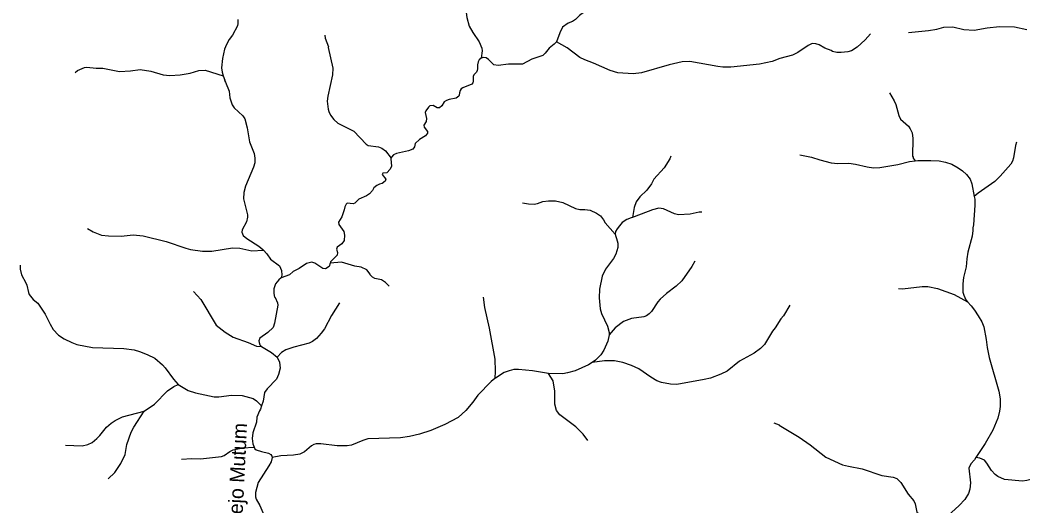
# Model space of a CAD drawing. Extents: x 280.4 to 335.6, y 8893.9 to 8949.5.
# Drawn here: x 296.15 to 309.86, y 8907.81 to 8914.46 of the extents above; entities that cross this region are included whole.
import ezdxf
from ezdxf.enums import TextEntityAlignment as Align

# ---------------------------------------------------------------- set-up
doc = ezdxf.new("R2010")
doc.units = 0
doc.header["$LTSCALE"] = 0.064
doc.layers.add('61', color=7, linetype='Continuous')
doc.layers.add('7', color=7, linetype='Continuous', lineweight=25)

msp = doc.modelspace()

# ---------------------------------------------------------------- linework, layer by layer
at = {"layer": '7'}
for points in [[(301.8848, 8915.449), (301.8864, 8915.4467), (301.9188, 8915.4138), (301.9677, 8915.3402), (302.0339, 8915.2193), (302.0645, 8915.1323), (302.0918, 8914.9596), (302.1185, 8914.8746), (302.1539, 8914.8139), (302.2065, 8914.7466), (302.2397, 8914.6644), (302.2609, 8914.4908), (302.2931, 8914.375), (302.3407, 8914.2893), (302.4311, 8914.1622), (302.4639, 8914.075), (302.4702, 8914.0389), (302.4566, 8913.937)], [(304.131, 8914.766), (304.1084, 8914.7319), (304.0128, 8914.6425), (303.8708, 8914.5712), (303.8022, 8914.5216), (303.7453, 8914.4656), (303.7067, 8914.4391), (303.647, 8914.4145), (303.5691, 8914.3586), (303.5316, 8914.284), (303.4874, 8914.1623)], [(299.1279, 8914.4677), (299.1312, 8914.4109), (299.1236, 8914.3786), (299.0589, 8914.2528), (299.013, 8914.191), (298.9749, 8914.1229), (298.9489, 8914.0583), (298.9185, 8913.9303), (298.9074, 8913.8032), (298.9143, 8913.7431), (298.9313, 8913.6938)], [(308.2977, 8914.2898), (308.572, 8914.3157), (308.6852, 8914.335), (308.7806, 8914.3588), (308.9026, 8914.3636), (309.0538, 8914.3285), (309.1977, 8914.3174), (309.3743, 8914.3527), (309.5424, 8914.3717), (309.7455, 8914.3651), (309.9167, 8914.3301)], [(300.3204, 8914.2503), (300.3254, 8914.21), (300.3674, 8914.0936), (300.3649, 8914.0806), (300.4296, 8913.7994), (300.4231, 8913.7082), (300.3596, 8913.4186), (300.3516, 8913.3507), (300.3628, 8913.2396), (300.3723, 8913.2066), (300.3969, 8913.1583), (300.44, 8913.0999), (300.4975, 8913.0484), (300.7149, 8912.9368), (300.8847, 8912.759), (300.9131, 8912.7414), (301.0536, 8912.7228), (301.0973, 8912.7065), (301.1489, 8912.6691), (301.2258, 8912.5692)], [(307.7771, 8914.2691), (307.7045, 8914.1858), (307.5982, 8914.0861), (307.5189, 8914.0364), (307.4698, 8914.0232), (307.3753, 8914.012), (307.3164, 8914.0152), (307.261, 8914.0289), (307.2411, 8914.0421), (307.1539, 8914.0725), (307.0773, 8914.1177), (307.0334, 8914.1343), (306.9818, 8914.1366), (306.9254, 8914.109), (306.7847, 8914.0132), (306.7133, 8913.9777), (306.5407, 8913.9308), (306.4328, 8913.8917), (306.2592, 8913.8523), (305.8713, 8913.8153), (305.7601, 8913.8154), (305.6929, 8913.8219), (305.3106, 8913.8914), (305.2028, 8913.8856), (305.0245, 8913.8436), (304.6503, 8913.7361), (304.5343, 8913.7225), (304.3232, 8913.7352), (304.2177, 8913.767), (303.9937, 8913.8693), (303.8747, 8913.9128), (303.805, 8913.946), (303.6341, 8914.0764), (303.4874, 8914.1623)], [(303.4874, 8914.1623), (303.4551, 8914.1282), (303.3866, 8914.0739), (303.3309, 8914.004), (303.2991, 8913.9746), (303.148, 8913.9219), (303.0196, 8913.8537), (302.8316, 8913.8538), (302.6888, 8913.8362), (302.6295, 8913.845), (302.5554, 8913.9189), (302.5262, 8913.9398), (302.4856, 8913.9454), (302.4566, 8913.937)], [(302.4566, 8913.937), (302.4297, 8913.9157), (302.415, 8913.8852), (302.4049, 8913.8432), (302.4056, 8913.7913), (302.4006, 8913.7659), (302.3907, 8913.7468), (302.3555, 8913.7078), (302.3461, 8913.6872), (302.3455, 8913.6227), (302.3406, 8913.6002), (302.3285, 8913.5793), (302.207, 8913.5297), (302.1838, 8913.5152), (302.1699, 8913.4944), (302.1613, 8913.4631), (302.1569, 8913.4291), (302.1493, 8913.4162), (302.1154, 8913.3916), (302.0188, 8913.3735), (301.9824, 8913.3589), (301.9525, 8913.3384), (301.9198, 8913.2837), (301.8885, 8913.2564), (301.8529, 8913.2569), (301.7987, 8913.289), (301.7559, 8913.2863), (301.737, 8913.2685), (301.7003, 8913.216), (301.6905, 8913.1945), (301.7074, 8913.1101), (301.7025, 8913.0715), (301.673, 8913.0196), (301.6776, 8912.9936), (301.7217, 8912.9356), (301.7231, 8912.9099), (301.6963, 8912.8753), (301.6126, 8912.8237), (301.5562, 8912.7713), (301.5447, 8912.7239), (301.5209, 8912.6932), (301.4614, 8912.669), (301.3006, 8912.6335), (301.2568, 8912.6123), (301.2296, 8912.5831), (301.2258, 8912.5692)], [(296.9063, 8913.7413), (296.9399, 8913.7685), (297.0324, 8913.8101), (297.0657, 8913.8135), (297.1923, 8913.7977), (297.285, 8913.8008), (297.5129, 8913.7545), (297.6634, 8913.7637), (297.7936, 8913.7831), (297.9407, 8913.7578), (298.1114, 8913.7102), (298.1989, 8913.6985), (298.3437, 8913.7096), (298.4791, 8913.733), (298.5971, 8913.7672), (298.6818, 8913.7705), (298.9313, 8913.6938)], [(298.9313, 8913.6938), (298.9512, 8913.6362), (298.9463, 8913.629), (298.961, 8913.6068), (299.0097, 8913.4857), (299.0228, 8913.3923), (299.0539, 8913.2986), (299.0811, 8913.2592), (299.1984, 8913.1467), (299.2266, 8913.1087), (299.2592, 8912.9836), (299.2885, 8912.7901), (299.3519, 8912.6317), (299.3645, 8912.5695), (299.3602, 8912.5055), (299.3439, 8912.4462), (299.2337, 8912.1871), (299.2127, 8912.1001), (299.2066, 8912.0145), (299.2621, 8911.7953), (299.2624, 8911.7625), (299.2486, 8911.6983), (299.1912, 8911.5873), (299.1857, 8911.557), (299.2018, 8911.5111), (299.2535, 8911.4703), (299.416, 8911.3669), (299.4722, 8911.3193), (299.4815, 8911.309)], [(308.0363, 8913.463), (308.1043, 8913.3518), (308.1257, 8913.3027), (308.1651, 8913.1529), (308.1891, 8913.1028), (308.2993, 8913.0049), (308.3225, 8912.9717), (308.3461, 8912.9157), (308.359, 8912.8357), (308.3527, 8912.5951), (308.3619, 8912.5821), (308.3629, 8912.567), (308.3884, 8912.5331)], [(309.7753, 8912.7859), (309.7601, 8912.743), (309.7313, 8912.5749), (309.718, 8912.5288), (309.6955, 8912.4889), (309.5498, 8912.321), (309.4769, 8912.2479), (309.252, 8912.09), (309.1964, 8912.0438)], [(301.2258, 8912.5692), (301.2237, 8912.5613), (301.2295, 8912.4603), (301.2129, 8912.4186), (301.1663, 8912.3688), (301.1141, 8912.3616), (301.1008, 8912.3476), (301.1523, 8912.2793), (301.1451, 8912.2531), (301.1022, 8912.2244), (301.0671, 8912.2145), (301.0313, 8912.1951), (300.9906, 8912.1609), (300.9729, 8912.1244), (300.9287, 8912.0808), (300.8909, 8912.0539), (300.7819, 8912.0078), (300.7298, 8911.9549), (300.7064, 8911.9441), (300.6263, 8911.9534), (300.6115, 8911.9399), (300.5922, 8911.904), (300.5832, 8911.8625), (300.5521, 8911.7665), (300.5052, 8911.6915), (300.512, 8911.6611), (300.5807, 8911.5679), (300.5899, 8911.5147), (300.582, 8911.4419), (300.5509, 8911.3954), (300.4893, 8911.3498), (300.4769, 8911.3259), (300.4921, 8911.2772), (300.4872, 8911.2413), (300.3989, 8911.1529), (300.3924, 8911.1306)], [(305.0481, 8912.5981), (305.0363, 8912.5609), (304.9583, 8912.4384), (304.8159, 8912.2793), (304.7844, 8912.2195), (304.722, 8912.1326), (304.6274, 8912.0408), (304.5756, 8911.9696), (304.5494, 8911.8954), (304.5243, 8911.759)], [(306.8115, 8912.6146), (306.9708, 8912.5822), (307.0861, 8912.5439), (307.2429, 8912.5048), (307.334, 8912.4943), (307.4826, 8912.499), (307.5721, 8912.4878), (307.7329, 8912.4509), (307.8209, 8912.4383), (307.908, 8912.4415), (308.151, 8912.4826), (308.3111, 8912.523), (308.3884, 8912.5331)], [(308.3884, 8912.5331), (308.4249, 8912.5379), (308.6037, 8912.539), (308.7188, 8912.5307), (308.8029, 8912.5136), (308.8899, 8912.4862), (308.9769, 8912.4362), (309.0371, 8912.3934), (309.0914, 8912.3439), (309.1409, 8912.2799), (309.166, 8912.2175), (309.1964, 8912.0438)], [(309.1964, 8912.0438), (309.2029, 8912.0066), (309.2065, 8911.9257), (309.1874, 8911.657), (309.1779, 8911.6171), (309.1793, 8911.5787), (309.1681, 8911.502), (309.1083, 8911.2845), (309.0943, 8911.1924), (309.0866, 8911.0806), (309.0511, 8910.9351), (309.0403, 8910.8495), (309.0419, 8910.7358), (309.0531, 8910.6966), (309.0837, 8910.6332), (309.1023, 8910.6046)], [(303.0215, 8911.9581), (303.102, 8911.9439), (303.1806, 8911.9394), (303.2285, 8911.9489), (303.3007, 8911.9741), (303.3775, 8911.987), (303.471, 8911.9856), (303.5714, 8911.963), (303.7473, 8911.8784), (303.8029, 8911.8675), (303.8754, 8911.8673), (303.945, 8911.8577), (304.0308, 8911.8181), (304.0857, 8911.7793), (304.1296, 8911.7232), (304.1508, 8911.6838), (304.2888, 8911.5274)], [(305.4717, 8911.8309), (305.4375, 8911.8302), (305.3147, 8911.8019), (305.1535, 8911.7939), (305.0973, 8911.8059), (304.9475, 8911.8764), (304.8859, 8911.8865), (304.7964, 8911.8643), (304.5494, 8911.7684), (304.5243, 8911.759)], [(304.5243, 8911.759), (304.5051, 8911.7533), (304.4477, 8911.7307), (304.3843, 8911.6877), (304.346, 8911.6444), (304.3156, 8911.6018), (304.2938, 8911.5641), (304.2888, 8911.5274)], [(297.0745, 8911.6054), (297.154, 8911.5621), (297.2672, 8911.517), (297.3619, 8911.5044), (297.5349, 8911.5011), (297.7004, 8911.5201), (297.8358, 8911.5043), (298.1509, 8911.4296), (298.4196, 8911.3375), (298.4827, 8911.3218), (298.6448, 8911.2976), (298.7732, 8911.2976), (299.057, 8911.3426), (299.1584, 8911.3366), (299.3208, 8911.3011), (299.4815, 8911.309)], [(304.2888, 8911.5274), (304.2957, 8911.4987), (304.3063, 8911.4683), (304.3224, 8911.4082), (304.3227, 8911.3767), (304.3224, 8911.3467), (304.2965, 8911.2558), (304.2657, 8911.1974), (304.1564, 8911.0528), (304.1098, 8910.9525), (304.0729, 8910.777), (304.0684, 8910.6602), (304.0826, 8910.508), (304.1024, 8910.4424), (304.1847, 8910.2687), (304.2038, 8910.1857), (304.2053, 8910.154)], [(299.4815, 8911.309), (299.5258, 8911.2601), (299.5764, 8911.1857), (299.701, 8911.0969), (299.7264, 8911.0309), (299.7294, 8910.9693), (299.7219, 8910.9308)], [(296.1529, 8911.1054), (296.1554, 8911.0494), (296.1705, 8910.9716), (296.2332, 8910.8637), (296.2461, 8910.831), (296.267, 8910.7295), (296.2787, 8910.7036), (296.3338, 8910.635), (296.3943, 8910.5837), (296.4961, 8910.4369), (296.5632, 8910.2962), (296.6072, 8910.225), (296.6781, 8910.1498), (296.7554, 8910.0998), (296.8597, 8910.0461), (296.9291, 8910.0207), (297.1411, 8909.9788), (297.5719, 8909.9676), (297.7136, 8909.9452), (297.7854, 8909.9256), (297.8909, 8909.8855), (297.9958, 8909.8313), (298.1023, 8909.7409), (298.1376, 8909.7009), (298.2503, 8909.5446), (298.3159, 8909.4711)], [(299.97, 8911.0586), (299.8862, 8911.0177), (299.8374, 8910.9731), (299.7219, 8910.9308)], [(300.3924, 8911.1306), (300.3802, 8911.089), (300.3282, 8911.0571), (300.294, 8911.0596), (300.182, 8911.1315), (300.1406, 8911.1454), (300.0701, 8911.1289), (299.97, 8911.0586)], [(301.1992, 8910.8191), (301.1499, 8910.867), (301.0957, 8910.9025), (301.0015, 8910.9247), (300.9688, 8910.9418), (300.9388, 8910.972), (300.9379, 8910.9827), (300.8954, 8911.0417), (300.8158, 8911.0796), (300.7283, 8911.0937), (300.5457, 8911.1459), (300.3924, 8911.1306)], [(305.3773, 8911.1621), (305.3371, 8911.0855), (305.1972, 8910.8918), (305.1208, 8910.8177), (304.9894, 8910.7162), (304.9042, 8910.6402), (304.8718, 8910.6027), (304.7866, 8910.4733), (304.7547, 8910.4381), (304.7165, 8910.414), (304.6782, 8910.3994), (304.513, 8910.3765), (304.403, 8910.3338), (304.2878, 8910.2476), (304.2053, 8910.154)], [(299.7219, 8910.9308), (299.692, 8910.9068), (299.6457, 8910.8485), (299.6239, 8910.783), (299.6207, 8910.7183), (299.6319, 8910.6687), (299.6402, 8910.6635), (299.673, 8910.5919), (299.6781, 8910.5583), (299.6333, 8910.3119), (299.6107, 8910.2524), (299.5397, 8910.1822), (299.4312, 8910.1068), (299.4178, 8910.0709), (299.4195, 8910.0466), (299.4322, 8910.0163), (299.4535, 8909.992)], [(308.1596, 8910.7854), (308.2175, 8910.7831), (308.4862, 8910.8134), (308.563, 8910.8134), (308.6955, 8910.7876), (308.9219, 8910.7046), (309.1023, 8910.6046)], [(298.5222, 8910.7441), (298.6231, 8910.6353), (298.8339, 8910.2842), (298.9573, 8910.1869), (299.0654, 8910.1204), (299.273, 8910.0492), (299.3849, 8909.998), (299.4535, 8909.992)], [(302.4854, 8910.6688), (302.5025, 8910.5246), (302.5677, 8910.2439), (302.6429, 8909.8185), (302.6481, 8909.6549), (302.643, 8909.5534)], [(300.5207, 8910.5884), (300.4094, 8910.4158), (300.3145, 8910.2366), (300.2711, 8910.1732), (300.207, 8910.1013), (300.1502, 8910.0596), (300.1043, 8910.038), (299.8947, 8909.9818), (299.7853, 8909.945), (299.7289, 8909.9094), (299.6692, 8909.8491)], [(306.6776, 8910.5565), (306.5874, 8910.4126), (306.5542, 8910.3724), (306.4746, 8910.2467), (306.4376, 8910.2029), (306.3292, 8910.0196), (306.2744, 8909.9652), (306.1904, 8909.9019), (305.9876, 8909.7904), (305.8171, 8909.6568), (305.7337, 8909.6158), (305.5898, 8909.5615), (305.5055, 8909.5394), (305.1292, 8909.4717), (305.0449, 8909.4777), (304.92, 8909.4989), (304.8599, 8909.5245), (304.7751, 8909.5733), (304.6135, 8909.6883), (304.5097, 8909.7349), (304.3944, 8909.775), (304.2777, 8909.7946), (304.1403, 8909.7979), (303.9733, 8909.7743)], [(309.1023, 8910.6046), (309.1556, 8910.5475), (309.198, 8910.4881), (309.2514, 8910.412), (309.2992, 8910.3292), (309.3278, 8910.2623), (309.36, 8910.0865), (309.3714, 8909.9803), (309.4016, 8909.8402), (309.5345, 8909.3813), (309.5505, 8909.2748), (309.5504, 8909.1709), (309.5422, 8909.1063), (309.5186, 8909.0118), (309.4521, 8908.8463), (309.3469, 8908.6682), (309.2186, 8908.4753)], [(304.2053, 8910.154), (304.1879, 8910.0667), (304.1327, 8909.9404), (304.0907, 8909.8809), (304.0214, 8909.8066), (303.9733, 8909.7743)], [(299.4535, 8909.992), (299.5912, 8909.9118), (299.6692, 8909.8491)], [(299.6692, 8909.8491), (299.7007, 8909.7779), (299.707, 8909.6961), (299.6877, 8909.6092), (299.6589, 8909.5454), (299.5323, 8909.4137), (299.496, 8909.362), (299.475, 8909.2446), (299.4538, 8909.182)], [(303.9733, 8909.7743), (303.9232, 8909.7407), (303.7435, 8909.6619), (303.6373, 8909.6314), (303.5706, 8909.6207), (303.3777, 8909.6242)], [(302.643, 8909.5534), (302.5951, 8909.5134), (302.4119, 8909.3251), (302.3441, 8909.2318), (302.2455, 8909.1172), (302.1435, 8909.0235), (301.9581, 8908.9275), (301.7684, 8908.8438), (301.614, 8908.794), (301.4783, 8908.7614), (301.3518, 8908.744), (300.9049, 8908.7281), (300.8378, 8908.7081), (300.6839, 8908.6448), (300.6257, 8908.6346), (300.4882, 8908.6336), (300.2652, 8908.6623), (300.1996, 8908.6592), (300.1677, 8908.6511), (300.1363, 8908.634), (300.039, 8908.5532), (299.9772, 8908.5211), (299.89, 8908.5057), (299.7173, 8908.4993), (299.5995, 8908.4727)], [(303.3777, 8909.6242), (303.3774, 8909.6242), (303.1575, 8909.6588), (302.9663, 8909.6795), (302.9007, 8909.6759), (302.8376, 8909.6616), (302.7696, 8909.6354), (302.6518, 8909.5608), (302.643, 8909.5534)], [(303.9134, 8908.7087), (303.8503, 8908.7943), (303.7503, 8908.8956), (303.533, 8909.0572), (303.4881, 8909.1192), (303.4638, 8909.2062), (303.4652, 8909.3804), (303.4389, 8909.5243), (303.3777, 8909.6242)], [(297.8514, 8909.1098), (297.9894, 8909.2062), (298.1683, 8909.3853), (298.2555, 8909.4464), (298.3159, 8909.4711)], [(298.3159, 8909.4711), (298.4519, 8909.3888), (298.5507, 8909.3568), (298.8053, 8909.3056), (298.8697, 8909.3054), (299.0418, 8909.3277), (299.1895, 8909.3211), (299.3384, 8909.2837), (299.3865, 8909.2492), (299.4538, 8909.182)], [(299.4538, 8909.182), (299.4382, 8909.1358), (299.4248, 8909.115), (299.3906, 8909.0253), (299.3832, 8908.9599), (299.3362, 8908.8103), (299.3249, 8908.7335), (299.3361, 8908.6619), (299.3525, 8908.615)], [(296.7755, 8908.6411), (297.001, 8908.6353), (297.0791, 8908.6503), (297.1367, 8908.6804), (297.2047, 8908.7334), (297.2449, 8908.7749), (297.3343, 8908.8885), (297.3971, 8908.9434), (297.4538, 8908.9814), (297.5512, 8909.0302), (297.8514, 8909.1098)], [(297.3571, 8908.1822), (297.4476, 8908.2696), (297.5323, 8908.3911), (297.5912, 8908.5169), (297.6118, 8908.6538), (297.6719, 8908.819), (297.7103, 8908.8913), (297.8514, 8909.1098)], [(306.459, 8908.9497), (306.5285, 8908.9233), (306.5319, 8908.9165), (306.8052, 8908.7547), (306.9552, 8908.647), (307.1689, 8908.4784), (307.397, 8908.376), (307.4782, 8908.3542), (307.6657, 8908.3199), (307.9329, 8908.2293), (308.0871, 8908.2065), (308.1367, 8908.1889), (308.1929, 8908.1345), (308.2914, 8907.9722), (308.3689, 8907.8813), (308.3882, 8907.8418), (308.4132, 8907.7272), (308.4647, 8907.6838), (308.6475, 8907.632), (308.7206, 8907.5778), (308.7814, 8907.5098)], [(298.3596, 8908.4503), (298.5018, 8908.4593), (298.6178, 8908.4578), (298.908, 8908.4868), (298.9422, 8908.5022), (299.0226, 8908.5584), (299.0649, 8908.5798), (299.1959, 8908.608), (299.3525, 8908.615)], [(299.3525, 8908.615), (299.3629, 8908.5936), (299.3803, 8908.5806), (299.4527, 8908.5557), (299.5502, 8908.5359), (299.5817, 8908.5168), (299.5958, 8908.4948), (299.5995, 8908.4727)], [(299.5995, 8908.4727), (299.5837, 8908.4131), (299.5528, 8908.3621), (299.4083, 8908.1337), (299.3696, 8907.9971), (299.3708, 8907.936), (299.3805, 8907.905), (299.429, 8907.8189), (299.47, 8907.7227), (299.4831, 8907.6637), (299.483, 8907.6204), (299.4626, 8907.5439), (299.4338, 8907.4796), (299.354, 8907.3549), (299.2995, 8907.2988), (299.1586, 8907.1913), (299.1244, 8907.1555), (299.1108, 8907.1), (299.1368, 8907.0604), (299.1432, 8907.0543)], [(309.2186, 8908.4753), (309.198, 8908.4444), (309.1519, 8908.3867), (309.1237, 8908.3291), (309.1458, 8908.1266), (309.1345, 8908.0412), (309.1199, 8907.9837), (309.0669, 8907.9006), (308.9891, 8907.8181), (308.835, 8907.6767), (308.8121, 8907.633), (308.7815, 8907.5305), (308.7814, 8907.5098)], [(310.5652, 8908.1229), (310.502, 8908.1416), (310.325, 8908.1774), (310.1463, 8908.1938), (310.0229, 8908.1858), (309.9163, 8908.1592), (309.8559, 8908.1507), (309.6104, 8908.173), (309.5179, 8908.2148), (309.4827, 8908.2408), (309.434, 8908.2967), (309.3709, 8908.3975), (309.3356, 8908.439), (309.2745, 8908.4639), (309.2186, 8908.4753)]]:
    msp.add_lwpolyline(points, dxfattribs=at)

# ---------------------------------------------------------------- texts
at = {"layer": '61'}
msp.add_text('Brejo Mutum', height=0.2, rotation=87.149, dxfattribs=at).set_placement((299.2202, 8908.1845), align=Align.CENTER)

doc.saveas('drawing.dxf')
